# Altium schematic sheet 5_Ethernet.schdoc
size 309 x 223 mm; Symbol: Artery_A4; Device: Artery_A4; Company: Artery Technology; Drawed: SD; Version: 1.0; Page Size: A4; @Project Name: AT-START-F457; @Page Count: 5; @Update Date: 2025-01-20; @Create Date: 2024-08-26; @Schematic Name: AT-START-F457 V1.0; @Page No: 5; @Page Name: Ethernet; @Board Name: AT-START-F457_v1.0; @Create Time: 16:51:53; @Update Time: 15:25:27
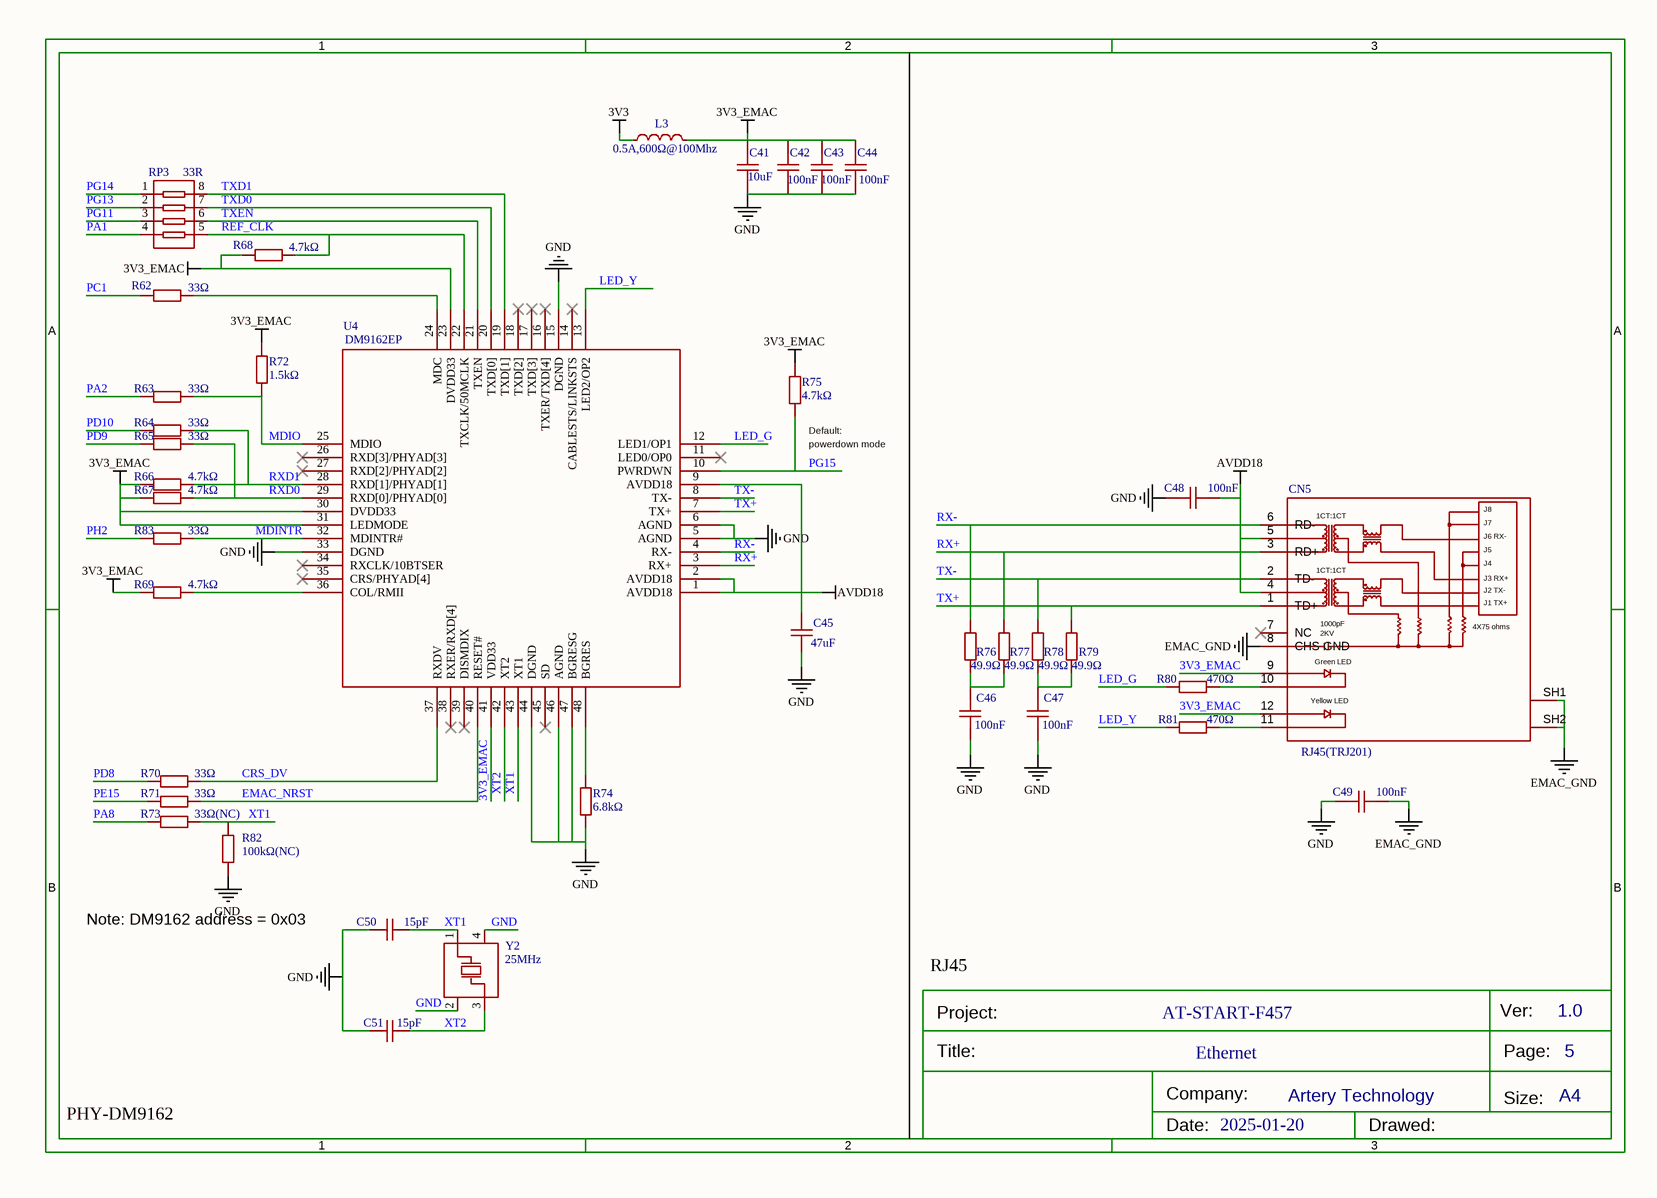
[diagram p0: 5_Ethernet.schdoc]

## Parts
C41  10uF  [C0603]
C42  100nF  [C0603]
C43  100nF  [C0603]
C44  100nF  [C0603]
C45  47uF  [C0805]
C46  100nF  [C0603]
C47  100nF  [C0603]
C48  100nF  [C0603]
C49  100nF  [C0603]
C50  15pF  [C0603]
C51  15pF  [C0603]
CN5  RJ45(TRJ201)  [RJ45-TH_HR911105A]
L3  0.5A,600Ω@100Mhz  [0603_L]
R62  33Ω  [R0603]
R63  33Ω  [R0603]
R64  33Ω  [R0603]
R65  33Ω  [R0603]
R66  4.7kΩ  [R0603]
R67  4.7kΩ  [R0603]
R68  4.7kΩ  [R0603]
R69  4.7kΩ  [R0603]
R70  33Ω  [R0603]
R71  33Ω  [R0603]
R72  1.5kΩ  [R0603]
R73  33Ω(NC)  [R0603]
R74  6.8kΩ  [R0603]
R75  4.7kΩ  [R0603]
R76  49.9Ω  [R0603]
R77  49.9Ω  [R0603]
R78  49.9Ω  [R0603]
R79  49.9Ω  [R0603]
R80  470Ω  [R0603]
R81  470Ω  [R0603]
R82  100kΩ(NC)  [R0603]
R83  33Ω  [R0603]
RP3  33R  [0603*4,8P4R]
U4  DM9162EP  [LQFP48_7*7]
Y2  25MHz  [OSC-SMD_4P-L3.2-W2.5-BL]

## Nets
3V3: L3.1
3V3_EMAC: C41.1 C42.1 C43.1 C44.1 CN5.9 CN5.12 L3.2 R66.1 R67.1 R68.1 R69.1 R72.2 R75.2 U4.23(DVDD33) U4.30(DVDD33) U4.31(LEDMODE) U4.41(VDD33)
AVDD18: C45.2 C48.2 CN5.4 CN5.5 U4.1(AVDD18) U4.2(AVDD18) U4.9(AVDD18)
EMAC_GND: C49.2 CN5.8(CHS_GND) CN5.SH1 CN5.SH2
GND: C41.2 C42.2 C43.2 C44.2 C45.1 C46.2 C47.2 C48.1 C49.1 C50.2 C51.2 R74.1 R82.2 U4.5(AGND) U4.6(AGND) U4.15(DGND) U4.33(DGND) U4.44(DGND) U4.46(AGND) U4.47(BGRESG) Y2.2(GND) Y2.4(GND)
CRS_DV: R70.2 U4.37(RXDV)
EMAC_NRST: R71.2 U4.40(RESET#)
LED_G: R80.2 U4.12(LED1/OP1)
LED_Y: R81.2 U4.13(LED2/OP2)
MDINTR: R83.2 U4.32(MDINTR#)
MDIO: R63.2 R72.1 U4.25(MDIO)
PA1: RP3.4
PA2: R63.1
PA8: R73.1
PC1: R62.1
PD8: R70.1
PD9: R65.1
PD10: R64.1
PE15: R71.1
PG11: RP3.3
PG13: RP3.2
PG14: RP3.1
PG15: R75.1 U4.10(PWRDWN)
PH2: R83.1
REF_CLK: R68.2 RP3.5 U4.22(TXCLK/50MCLK)
RX+: CN5.3(RD+) R77.2 U4.3(RX+)
RX-: CN5.6(RD-) R76.2 U4.4(RX-)
RXD0: R65.2 R67.2 U4.29(RXD[0]/PHYAD[0])
RXD1: R64.2 R66.2 U4.28(RXD[1]/PHYAD[1])
TX+: CN5.1(TD+) R79.2 U4.7(TX+)
TX-: CN5.2(TD-) R78.2 U4.8(TX-)
TXD0: RP3.7 U4.20(TXD[0])
TXD1: RP3.8 U4.19(TXD[1])
TXEN: RP3.6 U4.21(TXEN)
XT1: C50.1 R73.2 R82.1 U4.43(XT1) Y2.1(OSC1)
XT2: C51.1 U4.42(XT2) Y2.3(OSC2)
NetC46_1: C46.1 R76.1 R77.1
NetC47_1: C47.1 R78.1 R79.1
NetCN5_10: CN5.10 R80.1
NetCN5_11: CN5.11 R81.1
NetR62_2: R62.2 U4.24(MDC)
NetR69_2: R69.2 U4.36(COL/RMII)
NetR74_2: R74.2 U4.48(BGRES)

Not connected (* = marked no-connect by the designer): CN5 7(NC)*; U4 11(LED0/OP0)* 14(CABLESTS/LINKSTS)* 16(TXER/TXD[4])* 17(TXD[3])* 18(TXD[2])* 26(RXD[3]/PHYAD[3])* 27(RXD[2]/PHYAD[2])* 34(RXCLK/10BTSER)* 35(CRS/PHYAD[4])* 38(RXER/RXD[4])* 39(DISMDIX)* 45(SD)*

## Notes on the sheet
- (near R75) Default:
- (near R75) powerdown mode
- (near R82) Note: DM9162 address = 0x03
- RJ45
- AT-START-F457
- PHY-DM9162
- 2025-01-20

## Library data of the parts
C41 = CL10A106KP8NNNC: Manufacturer: SAMSUNG(三星); Add into BOM: yes; Tolerance: ±10%; Voltage Rated: 10V; Temperature Coefficient: X5R; Origin Footprint: 0603_C-M
C42-C44 C46-C49 = CC0603KRX7R9BB104: Manufacturer: YAGEO(国巨); Add into BOM: yes; Tolerance: ±10%; Voltage Rated: 50V; Temperature Coefficient: X7R; Origin Footprint: 0603_C-M
C45 = CL21A476MQYNNNE: Manufacturer: SAMSUNG(三星); Add into BOM: yes; Tolerance: ±20%; Voltage Rated: 6.3V; Temperature Coefficient: X5R
C50 C51 = CL10C150JB8NNNC: Manufacturer: SAMSUNG(三星); Add into BOM: yes; Tolerance: ±5%; Voltage Rated: 50V; Temperature Coefficient: C0G
CN5 = HR911105A: Manufacturer: HANRUN; Paste Type: expand; Convert to PCB: yes
L3 = 0.5A,600Ω@100Mhz: Convert to PCB: yes
R62-R65 R70 R71 R73 R83 = 0603WAF330JT5E: Manufacturer: UNI-ROYAL(厚声); Add into BOM: yes; Tolerance: ±1%; Power(Watts): 100mW; Temperature Coefficient: ±100ppm/℃; Overload Voltage (Max): 75V
R66-R69 R75 = 0603WAF4701T5E: Manufacturer: UNI-ROYAL(厚声); Add into BOM: yes; Tolerance: ±1%; Power(Watts): 100mW; Temperature Coefficient: ±100ppm/℃; Overload Voltage (Max): 75V
R72 = 0603WAF1501T5E: Manufacturer: UNI-ROYAL(厚声); Add into BOM: yes; Tolerance: ±1%; Power(Watts): 100mW; Temperature Coefficient: ±100ppm/℃; Overload Voltage (Max): 75V
R74 = 0603WAF6801T5E: Manufacturer: UNI-ROYAL(厚声); Add into BOM: yes; Tolerance: ±1%; Power(Watts): 100mW; Temperature Coefficient: ±100ppm/℃; Overload Voltage (Max): 75V
R76-R79 = 0603WAF499JT5E: Manufacturer: UNI-ROYAL(厚声); Add into BOM: yes; Tolerance: ±1%; Power(Watts): 100mW; Temperature Coefficient: ±100ppm/℃; Overload Voltage (Max): 75V
R80 R81 = 0603WAF4700T5E: Manufacturer: UNI-ROYAL(厚声); Add into BOM: yes; Tolerance: ±1%; Power(Watts): 100mW; Temperature Coefficient: ±100ppm/℃; Overload Voltage (Max): 75V
R82 = 0603WAF1003T5E: Manufacturer: UNI-ROYAL(厚声); Add into BOM: yes; Tolerance: ±1%; Power(Watts): 100mW; Temperature Coefficient: ±100ppm/℃; Overload Voltage (Max): 75V
RP3 = 33R: Convert to PCB: yes
U4 = DM9162EP: Convert to PCB: yes
Y2 = X322525MOB4SI: Manufacturer: YXC(扬兴晶振); Add into BOM: yes; Crystal Type: 贴片晶振; Normal temperature Frequency Tolerance: ±10ppm; External load capacitor: 12pF; Frequency Stability(Full temperature range): ±20ppm; Frequency Stability: ±50ppm; Load Capacitance: 20pF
